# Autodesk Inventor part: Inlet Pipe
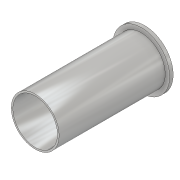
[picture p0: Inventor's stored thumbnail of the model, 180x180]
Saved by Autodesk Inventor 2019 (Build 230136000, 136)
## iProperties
Created: 2019-11
Part Number: Inlet Pipe
Material: Steel, Carbon
Document SubType Name: Modeling
Designer: Admin
Density: 7.85 g/cm^3
Appearance: Semi-Polished
Author: Admin
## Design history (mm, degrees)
sketch "Sketch1"
  geometry: C1 r 127.254 at (0, 0); C2 r 136.525 at (0, 0); 1 further point
  constraints: 2 centre point, 2 coincident
  dimensions: "d0" = 254.508 diameter of C1; "d1" = 273.05 diameter of C2
extrude "Extrusion1" new body sketch "Sketch1" distance "d2" = 625; taper "d3" = 0 deg
sketch "Sketch2"
  geometry: C1 r 136.525 at (0, 0) reference; C2 r 162 at (0, 0); 1 further point
  constraints: 1 centre point, 1 coincident
  dimensions: "d4" = 324 diameter of C2
extrude "Extrusion2" join sketch "Sketch2" distance "d5" = 20; taper "d6" = 0 deg
body "Solid1"
